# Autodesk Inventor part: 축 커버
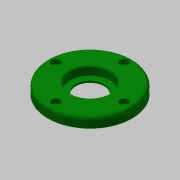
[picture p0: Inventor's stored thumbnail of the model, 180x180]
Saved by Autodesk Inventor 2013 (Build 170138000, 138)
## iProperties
Created: 2015-10
Part Number: 축 커버
Document SubType Name: Modeling
Designer: mdu
Density: 1 g/cm^3
Material: 일반
Author: mdu
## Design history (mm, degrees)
sketch "스케치1"
  geometry: C1 r 40 at (0, 0) reference; C2 r 26 at (0, 0) reference; 1 further point
  node "참조1"
  node "참조2"
extrude "돌출1" new body sketch "스케치1" distance "d0" = 10; taper "d1" = 0 deg
extrude "돌출2" join sketch "스케치1" distance "d2" = 3; taper "d3" = 0 deg
hole "구멍1" diameter "d6" = 27; stored, may be unused: countersink angle "d10" = 90 deg, drill point angle "d12" = 118 deg; dims "d7" = 6, "d8" = 38, "d9" = 8.3, "d11" = 8, "d33" = 10, "d34" = 10
sketch "스케치2"
  geometry: C1 r 20 at (0, 0); 1 further point
  constraints: 1 centre point, 1 coincident
  dimensions: "d13" = 40 diameter of C1
extrude "돌출3" cut sketch "스케치2" distance "d14" = 3; taper "d15" = 0 deg
sketch "스케치3"
  geometry: C1 r 1.621 at (0, 32.5) reference; 1 further point
hole "구멍2" sketch "스케치3" at (0, 32.5) diameter "d16" = 4.5; stored, may be unused: countersink angle "d20" = 90 deg, drill point angle "d22" = 118 deg; dims "d17" = 6, "d18" = 8, "d19" = 4.4, "d21" = 8
fillet "모깎기1" dims "d26" = 3, "d27" = 0.3
chamfer "모따기1" distance "d28" = 1; stored, may be unused: second distance "d29" = 2, angle "d30" = 45 deg
chamfer "모따기2" distance "d31" = 0.8; stored, may be unused: second distance "d32" = 2, angle "d35" = 30 deg
node "솔리드1"
pattern_circular "원형 패턴1" dims angle "d24" = 360 deg
node "참조3"
